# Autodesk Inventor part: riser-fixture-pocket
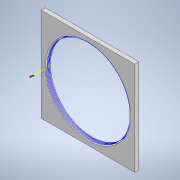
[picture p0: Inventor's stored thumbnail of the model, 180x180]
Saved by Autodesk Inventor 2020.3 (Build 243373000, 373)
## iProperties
Created: 2020-07
Part Number: riser-fixture-pocket
Material: Generic
Document SubType Name: Modeling
Designer: e
Density: 1 g/cm^3
Appearance: Default
Author: e
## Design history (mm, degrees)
sketch "Sketch1"
  geometry: L1 (-56.6, 56.6)-(56.6, 56.6); L2 (56.6, 56.6)-(56.6, -56.6); L3 (56.6, -56.6)-(-56.6, -56.6); L4 (-56.6, -56.6)-(-56.6, 56.6); C1 r 51.6 at (0, 0); 1 further point
  constraints: 8 end point, 2 parallel, 1 centre point, 1 coincident, 1 horizontal, 1 perpendicular
  dimensions: "d0" = 103.2 diameter of C1; "d1" = 5 distance edge to line of C1 L1; "d2" = 5 distance edge to line of C1 L4; "d3" = 5 distance edge to line of C1 L2; "d4" = 5 distance edge to line of C1 L3
extrude "Extrusion1" new body sketch "Sketch1" distance "d5" = 5; taper "d6" = 0 deg
body "Solid1"
